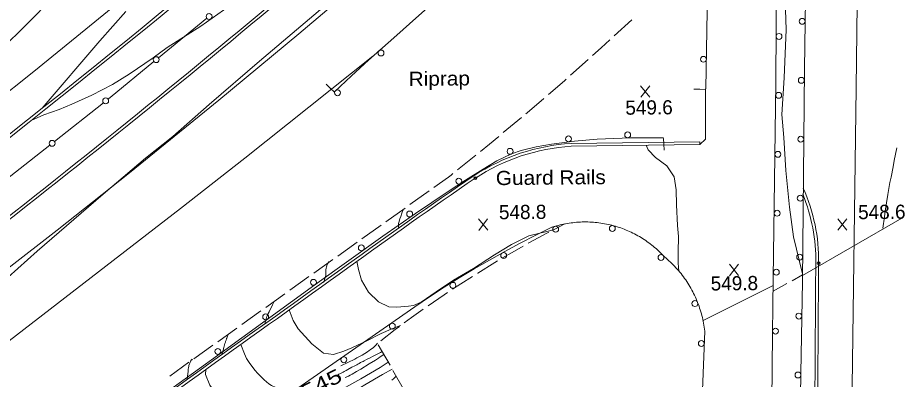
# Model space of a CAD drawing. Extents: x 2361284 to 2366480, y 6976556 to 6985346.
# Drawn here: x 2364184.5 to 2364482.3, y 6978961.5 to 6979084.2 of the extents above; entities that cross this region are included whole.
import ezdxf
from ezdxf.enums import TextEntityAlignment as Align

# ---------------------------------------------------------------- set-up
doc = ezdxf.new("R2010")
doc.units = 0
doc.header["$LTSCALE"] = 1.9
doc.header["$PDMODE"] = 32
doc.header["$PDSIZE"] = 0.95
for name, color, linetype, lineweight in [('12', 7, 'Continuous', 13), ('13', 7, 'Continuous', 13), ('14', 7, 'Continuous', 13), ('17', 7, 'Continuous', 13), ('24', 7, 'Continuous', 13), ('3', 7, 'Continuous', 13), ('5', 7, 'Continuous', 13), ('8', 7, 'Continuous', 13)]:
    doc.layers.add(name, color=color, linetype=linetype, lineweight=lineweight)

msp = doc.modelspace()

# ---------------------------------------------------------------- linework, layer by layer
at = {"layer": '12'}
for p, q in [((2364398.74, 6979057.25), (2364395.623, 6979061.101)), ((2364395.66, 6979057.221), (2364398.703, 6979061.13)), ((2364343.816, 6979012.086), (2364340.699, 6979015.937)), ((2364340.736, 6979012.057), (2364343.779, 6979015.966)), ((2364465.542, 6979012.113), (2364462.425, 6979015.964)), ((2364462.462, 6979012.084), (2364465.505, 6979015.993)), ((2364428.837, 6978996.693), (2364425.72, 6979000.544)), ((2364425.757, 6978996.664), (2364428.8, 6979000.573))]:
    msp.add_line(p, q, dxfattribs=at)
for points in [[(2364390.836, 6979256.813), (2364388.279, 6979254.359), (2364381.782, 6979248.668), (2364361.222, 6979231.731), (2364346.825, 6979220.903), (2364336.657, 6979213.196), (2364322.68, 6979202.352), (2364301.098, 6979184.517), (2364286.575, 6979173.257), (2364271.051, 6979161.92), (2364257.258, 6979150.698), (2364242.084, 6979137.233), (2364226.838, 6979123.107), (2364209.815, 6979105.355), (2364202.006, 6979096.9), (2364190.718, 6979085.091), (2364175.717, 6979070.308)], [(2364308.039, 6978970.921), (2364307.455, 6978970.626), (2364306.288, 6978970.035), (2364304.707, 6978969.231), (2364303.918, 6978968.828), (2364302.734, 6978968.221), (2364301.947, 6978967.815), (2364301.553, 6978967.611), (2364300.963, 6978967.304), (2364300.715, 6978967.174), (2364300.221, 6978966.913), (2364299.727, 6978966.651), (2364299.398, 6978966.474), (2364298.742, 6978966.12), (2364297.76, 6978965.585), (2364296.45, 6978964.871), (2364295.795, 6978964.515), (2364295.139, 6978964.16), (2364294.811, 6978963.984), (2364294.317, 6978963.721), (2364293.916, 6978963.51), (2364293.38, 6978963.23), (2364293.113, 6978963.089)], [(2364241.905, 6978961.452), (2364242.176, 6978963.465), (2364242.242, 6978964.098), (2364242.317, 6978964.944), (2364242.368, 6978965.367), (2364242.395, 6978965.529), (2364242.482, 6978965.909), (2364242.559, 6978966.19), (2364242.75, 6978966.783), (2364242.913, 6978967.221), (2364243.085, 6978967.62), (2364243.171, 6978967.796), (2364243.296, 6978968.021), (2364243.402, 6978968.173), (2364243.453, 6978968.229), (2364243.523, 6978968.285), (2364243.588, 6978968.305), (2364243.617, 6978968.3), (2364243.669, 6978968.257), (2364243.692, 6978968.219), (2364243.722, 6978968.14)], [(2364280.776, 6978956.42), (2364279.96, 6978955.963), (2364273.921, 6978952.605), (2364268.887, 6978949.857), (2364263.911, 6978948.44), (2364259.677, 6978948.83), (2364256.337, 6978950.918), (2364253.354, 6978954.28), (2364249.664, 6978959.525), (2364248.21, 6978963.132), (2364248.313, 6978964.863)]]:
    msp.add_lwpolyline(points, dxfattribs=at)
at = {"layer": '13'}
for points in [[(2364189.118, 6979049.315), (2364193.41, 6979051.236), (2364198.573, 6979053.035), (2364202.826, 6979054.845), (2364209.687, 6979057.9), (2364216.613, 6979061.546), (2364222.309, 6979065.07), (2364230.397, 6979070.598), (2364235.205, 6979074.095), (2364246.626, 6979081.363), (2364254.275, 6979086.755), (2364264.493, 6979094.404), (2364273.377, 6979101.289), (2364290.551, 6979115.803), (2364301.095, 6979123.833), (2364309.142, 6979129.48), (2364318.822, 6979136.882), (2364328.426, 6979143.884), (2364338.213, 6979151.557), (2364351.171, 6979162.372), (2364361.579, 6979171.05), (2364369.221, 6979177.283), (2364383.332, 6979186.649)], [(2364374.42, 6979177.413), (2364371.437, 6979173.564), (2364366.886, 6979168.361), (2364360.579, 6979161.601), (2364353.982, 6979154.957), (2364341.554, 6979140.949), (2364332.732, 6979131.734), (2364325.931, 6979124.399), (2364320.317, 6979118.526), (2364312.96, 6979111.774), (2364304.036, 6979102.7), (2364292.967, 6979092.024), (2364266.46, 6979069.42), (2364249.398, 6979054.798), (2364237.122, 6979043.94), (2364227.83, 6979036.592), (2364213.456, 6979024.384), (2364191.149, 6979005.012), (2364177.88, 6978993.245), (2364169.265, 6978985.383), (2364155.723, 6978972.782), (2364142.669, 6978960.479)], [(2364442.728, 6979133.74), (2364443.308, 6979130.686), (2364443.732, 6979123.889), (2364443.697, 6979117.019), (2364444.166, 6979105.623), (2364444.439, 6979093.695), (2364444.978, 6979080.169), (2364444.254, 6979063.751), (2364443.482, 6979051.334), (2364444.106, 6979043.508), (2364444.802, 6979032.394), (2364446.061, 6979019.866), (2364447.477, 6979009.849), (2364450.466, 6978997.307)], [(2364221.198, 6979086.261), (2364212.312, 6979076.337), (2364192.788, 6979053.48)], [(2364408.615, 6978998.209), (2364408.349, 6979000.865), (2364408.353, 6979004.627), (2364408.502, 6979010.018), (2364408.147, 6979013.675), (2364407.8, 6979020.732), (2364407.682, 6979025.801), (2364407.03, 6979030.185), (2364404.545, 6979033.992), (2364400.658, 6979036.815), (2364398.164, 6979039.351), (2364397.479, 6979040.915)], [(2364482.488, 6979040.007), (2364481.594, 6979035.738), (2364481.163, 6979033.6), (2364480.466, 6979030.051), (2364480.126, 6979028.274), (2364479.639, 6979025.605), (2364479.396, 6979024.19), (2364478.936, 6979021.355), (2364478.507, 6979018.516), (2364478.236, 6979016.621), (2364477.721, 6979012.827)], [(2364313.681, 6979012.887), (2364313.581, 6979013.253), (2364313.546, 6979013.439), (2364313.518, 6979013.716), (2364313.527, 6979013.991), (2364313.549, 6979014.126), (2364313.614, 6979014.425), (2364313.762, 6979015.02), (2364313.931, 6979015.614), (2364314.055, 6979016.008), (2364314.324, 6979016.793), (2364314.745, 6979017.919), (2364314.966, 6979018.474), (2364315.32, 6979019.303)], [(2364366.339, 6979012.398), (2364364.283, 6979011.818), (2364357.738, 6979010.236), (2364351.826, 6979007.199), (2364346.12, 6979003.744), (2364339.033, 6978999.057), (2364332.25, 6978995.153), (2364327.818, 6978992.24), (2364321.241, 6978987.658), (2364318.611, 6978986.573), (2364316.983, 6978986.317), (2364312.967, 6978985.959), (2364310.245, 6978986.093), (2364306.838, 6978987.841), (2364303.348, 6978991.028), (2364301.028, 6978995.176), (2364299.984, 6978998.816), (2364299.497, 6979001.571)], [(2364288.094, 6978994.553), (2364288.109, 6978994.491), (2364288.12, 6978994.461), (2364288.147, 6978994.428), (2364288.161, 6978994.425), (2364288.194, 6978994.441), (2364288.23, 6978994.487), (2364288.31, 6978994.654), (2364288.376, 6978994.835), (2364288.516, 6978995.293), (2364288.655, 6978995.816), (2364288.883, 6978996.74), (2364288.938, 6978997.027), (2364288.959, 6978997.219), (2364288.974, 6978997.603), (2364288.968, 6978997.987), (2364288.961, 6978998.5), (2364288.968, 6978998.756), (2364289.009, 6978999.14), (2364289.048, 6978999.331), (2364289.114, 6978999.574), (2364289.318, 6979000.18), (2364289.505, 6979000.653), (2364289.696, 6979001.061), (2364289.786, 6979001.217), (2364289.893, 6979001.357), (2364289.939, 6979001.391), (2364289.979, 6979001.397), (2364289.996, 6979001.389), (2364290.025, 6979001.349), (2364290.037, 6979001.317), (2364290.05, 6979001.251)], [(2364268.317, 6978980.383), (2364268.53, 6978981.288), (2364268.648, 6978981.738), (2364268.846, 6978982.405), (2364268.999, 6978982.844), (2364269.082, 6978983.061), (2364269.218, 6978983.383), (2364269.427, 6978983.807), (2364269.725, 6978984.359), (2364269.866, 6978984.639), (2364270.912, 6978986.829), (2364271.415, 6978987.934)], [(2364314.236, 6978979.73), (2364311.027, 6978978.519), (2364307.701, 6978977.047), (2364302.834, 6978974.621), (2364297.696, 6978972.162), (2364295.057, 6978971.038), (2364291.539, 6978969.884), (2364288.094, 6978970.382), (2364284.224, 6978973.524), (2364279.565, 6978978.61), (2364277.828, 6978981.464), (2364276.512, 6978985.072)], [(2364253.646, 6978969.864), (2364253.803, 6978970.368), (2364253.907, 6978970.705), (2364254.112, 6978971.378), (2364254.209, 6978971.7), (2364254.272, 6978971.915), (2364254.397, 6978972.346), (2364254.765, 6978973.64), (2364254.89, 6978974.071), (2364254.954, 6978974.286), (2364254.984, 6978974.384), (2364255.046, 6978974.58), (2364255.111, 6978974.775), (2364255.156, 6978974.904), (2364255.249, 6978975.161), (2364255.321, 6978975.353), (2364255.371, 6978975.481), (2364255.472, 6978975.735), (2364255.523, 6978975.862), (2364255.628, 6978976.116), (2364255.734, 6978976.369), (2364255.95, 6978976.875)], [(2364278.147, 6978958.386), (2364277.559, 6978958.23), (2364276.379, 6978958.089), (2364274.434, 6978958.129), (2364273.46, 6978958.285), (2364272.003, 6978958.737), (2364270.55, 6978959.451), (2364269.674, 6978960.012), (2364268.048, 6978961.331), (2364265.915, 6978963.455), (2364264.928, 6978964.591), (2364262.947, 6978967.172), (2364262.1, 6978968.564), (2364261.335, 6978970.11), (2364260.095, 6978973.305)], [(2364306.422, 6978973.765), (2364305.972, 6978973.221), (2364305.738, 6978972.959), (2364305.371, 6978972.583), (2364304.977, 6978972.233), (2364304.768, 6978972.069), (2364304.013, 6978971.518), (2364303.632, 6978971.251), (2364303.056, 6978970.859), (2364302.182, 6978970.294), (2364301.295, 6978969.754), (2364300.846, 6978969.494), (2364299.938, 6978968.993), (2364299.478, 6978968.753), (2364298.782, 6978968.403), (2364294.065, 6978966.098)], [(2364308.599, 6978969.937), (2364307.39, 6978969.126), (2364306.78, 6978968.729), (2364305.734, 6978968.063), (2364303.629, 6978966.749), (2364300.773, 6978964.98), (2364299.334, 6978964.114), (2364297.879, 6978963.274), (2364297.144, 6978962.867), (2364296.599, 6978962.594), (2364295.859, 6978962.257), (2364295.492, 6978962.082)], [(2364310.094, 6978967.311), (2364307.361, 6978965.485), (2364300.827, 6978961.692), (2364294.749, 6978958.233), (2364283.845, 6978952.339), (2364276.756, 6978947.872), (2364270.744, 6978944.895), (2364264.9, 6978942.21), (2364257.222, 6978937.836), (2364250.828, 6978934.915), (2364243.071, 6978931.401), (2364238.186, 6978929.914), (2364233.872, 6978929.283), (2364230.815, 6978929.874), (2364226.961, 6978931.318), (2364223.077, 6978933.891), (2364219.899, 6978936.801), (2364218.379, 6978938.837), (2364217.621, 6978942.899)], [(2364311.416, 6978964.983), (2364308.154, 6978963.122), (2364302.186, 6978959.634), (2364294.819, 6978955.094), (2364287.877, 6978951.128), (2364281.245, 6978948.125), (2364274.609, 6978944.361), (2364268.898, 6978941.378), (2364257.114, 6978935.485), (2364248.364, 6978930.041), (2364237.737, 6978925.62), (2364232.314, 6978922.668), (2364226.59, 6978919.904), (2364223.296, 6978919.262), (2364220.193, 6978919.583), (2364217.032, 6978920.683), (2364213.178, 6978923.136), (2364209.185, 6978926.608), (2364206.942, 6978928.997), (2364206.122, 6978930.039), (2364204.857, 6978933.768)], [(2364312.789, 6978962.566), (2364312.144, 6978961.939), (2364311.814, 6978961.634), (2364311.31, 6978961.188)]]:
    msp.add_lwpolyline(points, dxfattribs=at)
at = {"layer": '14'}
for points in [[(2364471.751, 6979300.826), (2364470.266, 6979192.976), (2364468.687, 6979060.443), (2364467.19, 6978950.713), (2364465.398, 6978823.599), (2364465.014, 6978782.341), (2364464.713, 6978727.329), (2364464.476, 6978699.823), (2364463.104, 6978583.283), (2364461.505, 6978460.062), (2364461.304, 6978437.786), (2364461.091, 6978393.234)], [(2364420.159, 6979267.113), (2364400.723, 6979248.336), (2364390.885, 6979239.073), (2364367.462, 6979217.462), (2364355.655, 6979206.764), (2364337.799, 6979190.876), (2364315.598, 6979171.486), (2364300.731, 6979158.638), (2364270.855, 6979133.106), (2364244.209, 6979110.62), (2364230.829, 6979099.447), (2364210.669, 6979082.791), (2364189.937, 6979065.945), (2364176.031, 6979054.822), (2364148.013, 6979032.833), (2364126.906, 6979016.585), (2364112.779, 6979005.83), (2364084.388, 6978984.496), (2364056.021, 6978963.478), (2364041.79, 6978953.033), (2364020.372, 6978937.464), (2363990.222, 6978915.934), (2363975.045, 6978905.311), (2363972.005, 6978903.232)], [(2363951.494, 6978832.723), (2363965.118, 6978841.916), (2363992.242, 6978860.482), (2364021.619, 6978880.939), (2364036.247, 6978891.253), (2364058.115, 6978906.831), (2364078.805, 6978921.811), (2364092.528, 6978931.892), (2364119.847, 6978952.23), (2364146.002, 6978972.008), (2364163.349, 6978985.309), (2364197.851, 6979012.166), (2364222.356, 6979031.614), (2364234.536, 6979041.425), (2364252.715, 6979056.252), (2364279.783, 6979078.749), (2364309.686, 6979104.155), (2364329.473, 6979121.256), (2364342.603, 6979132.728), (2364368.725, 6979155.838), (2364391.388, 6979176.238), (2364402.645, 6979186.517), (2364419.438, 6979202.042)]]:
    msp.add_lwpolyline(points, dxfattribs=at)
at = {"layer": '17'}
for points in [[(2364417.758, 6979060.079), (2364418.136, 6979086.513), (2364418.465, 6979112.948), (2364419.076, 6979168.637), (2364419.686, 6979224.326), (2364420.178, 6979269.333), (2364420.68, 6979314.33)], [(2364444.353, 6979307.846), (2364443.795, 6979259.247), (2364443.147, 6979210.649), (2364442.492, 6979174.41), (2364441.856, 6979138.163), (2364441.648, 6979100.168), (2364441.439, 6979062.174), (2364441.005, 6979028.918), (2364440.571, 6978995.663), (2364440.44, 6978986.341), (2364440.319, 6978977.008), (2364439.788, 6978919.211), (2364439.328, 6978861.403), (2364438.813, 6978806.165), (2364438.298, 6978750.917), (2364438.11, 6978727.544), (2364437.983, 6978704.162), (2364438.297, 6978676.313), (2364438.802, 6978648.466), (2364438.849, 6978604.574), (2364438.917, 6978560.692), (2364439.979, 6978526.851), (2364441.96, 6978493.038)], [(2364446.359, 6978672.98), (2364446.68, 6978699.164), (2364446.981, 6978725.358), (2364447.359, 6978766.605), (2364447.757, 6978807.84), (2364448.554, 6978870.221), (2364449.441, 6978932.593), (2364449.946, 6978963.65), (2364450.441, 6978994.716), (2364450.787, 6979030.811), (2364451.104, 6979066.906), (2364451.74, 6979106.275), (2364452.316, 6979145.642), (2364452.656, 6979190.848), (2364452.936, 6979236.063), (2364453.125, 6979270.877), (2364453.304, 6979305.691)], [(2364419.118, 6979172.568), (2364406.627, 6979160.979), (2364393.976, 6979149.567), (2364371.442, 6979129.902), (2364348.918, 6979110.207), (2364334.677, 6979097.561), (2364320.436, 6979084.904), (2364311.928, 6979077.354), (2364303.419, 6979069.802), (2364297.588, 6979064.496), (2364291.84, 6979059.101)], [(2364179.059, 6978918.752), (2364186.392, 6978923.582), (2364193.707, 6978928.451), (2364205.98, 6978936.638), (2364218.11, 6978945.034), (2364235.166, 6978957.307), (2364252.188, 6978969.62), (2364268.715, 6978981.587), (2364285.243, 6978993.556), (2364296.754, 6979001.844), (2364308.287, 6979010.105), (2364319.305, 6979017.751), (2364330.424, 6979025.247), (2364336.288, 6979029.073), (2364342.223, 6979032.809), (2364346.917, 6979035.584), (2364351.864, 6979037.981), (2364355.173, 6979039.173), (2364360.241, 6979040.441), (2364365.403, 6979041.31), (2364373.154, 6979042.354), (2364380.937, 6979043.038), (2364392.134, 6979043.484), (2364403.335, 6979043.431)], [(2364372.038, 6979014.582), (2364371.409, 6979014.496), (2364370.78, 6979014.39), (2364370.161, 6979014.284), (2364369.532, 6979014.158), (2364368.913, 6979014.022), (2364368.305, 6979013.876), (2364367.686, 6979013.73), (2364367.078, 6979013.565), (2364366.469, 6979013.389), (2364365.86, 6979013.203), (2364365.521, 6979013.09), (2364360.136, 6979010.458), (2364354.842, 6979007.728), (2364349.599, 6979004.898), (2364344.347, 6979001.987), (2364339.184, 6978998.979), (2364334.103, 6978995.89), (2364329.023, 6978992.722), (2364324.024, 6978989.444), (2364319.126, 6978986.097)], [(2364417.349, 6978977.9), (2364417.273, 6978978.559), (2364417.176, 6978979.218), (2364417.07, 6978979.877), (2364416.954, 6978980.536), (2364416.828, 6978981.195), (2364416.691, 6978981.844), (2364416.545, 6978982.494), (2364416.379, 6978983.142), (2364416.213, 6978983.78), (2364416.027, 6978984.429), (2364415.831, 6978985.067), (2364415.625, 6978985.695), (2364415.409, 6978986.333), (2364415.183, 6978986.951), (2364414.947, 6978987.579), (2364414.701, 6978988.196), (2364414.435, 6978988.814), (2364414.169, 6978989.421), (2364413.884, 6978990.029), (2364413.588, 6978990.626), (2364413.292, 6978991.223), (2364412.977, 6978991.81), (2364412.651, 6978992.387), (2364412.326, 6978992.964), (2364411.98, 6978993.541), (2364411.625, 6978994.107), (2364411.259, 6978994.664), (2364410.894, 6978995.22), (2364410.509, 6978995.767), (2364410.113, 6978996.303), (2364409.718, 6978996.839), (2364409.313, 6978997.365), (2364408.888, 6978997.881), (2364408.463, 6978998.387), (2364408.028, 6978998.893), (2364407.573, 6978999.389), (2364407.119, 6978999.875), (2364406.664, 6979000.359), (2364406.191, 6979000.825), (2364405.706, 6979001.29), (2364405.222, 6979001.746), (2364404.727, 6979002.191), (2364404.223, 6979002.636), (2364403.709, 6979003.061), (2364403.558, 6979003.19), (2364403.123, 6979003.656), (2364402.679, 6979004.112), (2364402.235, 6979004.548), (2364401.781, 6979004.994), (2364401.317, 6979005.43), (2364400.843, 6979005.845), (2364400.369, 6979006.261), (2364399.875, 6979006.666), (2364399.381, 6979007.061), (2364398.877, 6979007.457), (2364398.374, 6979007.832), (2364397.87, 6979008.207), (2364397.346, 6979008.572), (2364396.823, 6979008.917), (2364396.29, 6979009.262), (2364395.747, 6979009.597), (2364395.204, 6979009.922), (2364394.661, 6979010.237), (2364394.098, 6979010.541), (2364393.545, 6979010.846), (2364392.972, 6979011.131), (2364392.409, 6979011.405), (2364391.827, 6979011.67), (2364391.254, 6979011.924), (2364390.672, 6979012.169), (2364390.08, 6979012.413), (2364389.487, 6979012.638), (2364388.895, 6979012.852), (2364388.293, 6979013.056), (2364387.691, 6979013.251), (2364387.079, 6979013.435), (2364386.477, 6979013.609), (2364385.866, 6979013.773), (2364385.244, 6979013.917), (2364384.633, 6979014.062), (2364384.011, 6979014.196), (2364383.38, 6979014.31), (2364382.759, 6979014.424), (2364382.138, 6979014.518), (2364381.507, 6979014.602), (2364380.877, 6979014.686), (2364380.246, 6979014.74), (2364379.615, 6979014.804), (2364378.985, 6979014.838), (2364378.356, 6979014.872), (2364377.725, 6979014.896), (2364377.085, 6979014.9), (2364376.455, 6979014.904), (2364375.825, 6979014.888), (2364375.186, 6979014.862), (2364374.556, 6979014.836), (2364373.926, 6979014.79), (2364373.297, 6979014.724), (2364372.667, 6979014.658), (2364372.038, 6979014.582)], [(2364319.126, 6978986.097), (2364293.911, 6978968.587), (2364268.695, 6978951.075), (2364223.262, 6978919.672), (2364177.879, 6978888.188), (2364129.919, 6978854.212), (2364082.122, 6978819.995), (2364034.524, 6978785.94), (2363986.965, 6978751.846), (2363968.451, 6978738.519), (2363950.251, 6978724.765), (2363950.112, 6978724.654), (2363949.973, 6978724.533)], [(2364421.077, 6978403.814), (2364418.826, 6978449.135), (2364416.795, 6978494.459), (2364414.788, 6978545.683), (2364413.361, 6978596.922), (2364413.088, 6978633.012), (2364413.335, 6978669.105), (2364413.585, 6978689.099), (2364413.835, 6978709.092), (2364414.558, 6978774.993), (2364415.271, 6978840.903), (2364415.811, 6978889.38), (2364416.37, 6978937.859), (2364416.569, 6978957.882), (2364417.349, 6978977.9)]]:
    msp.add_lwpolyline(points, dxfattribs=at)
for centre in [(2364450.365, 6979082.968), (2364442.525, 6979077.858), (2364307.638, 6979072.21), (2364416.9, 6979070.092), (2364450.07, 6979062.962), (2364292.903, 6979058.728), (2364442.383, 6979057.851), (2364371.18, 6979043.094), (2364391.218, 6979044.453), (2364449.897, 6979042.963), (2364351.373, 6979038.855), (2364442.125, 6979037.852), (2364333.985, 6979028.763), (2364449.715, 6979022.965), (2364317.349, 6979017.611), (2364441.864, 6979017.853), (2364366.818, 6979012.447), (2364386.033, 6979012.69), (2364300.975, 6979006.101), (2364349.188, 6979003.527), (2364402.51, 6979002.849), (2364449.521, 6979002.965), (2364441.6, 6978997.855), (2364284.735, 6978994.422), (2364332.006, 6978993.399), (2364414.015, 6978987.207), (2364449.253, 6978982.973), (2364268.534, 6978982.691), (2364311.484, 6978979.57), (2364441.33, 6978977.857), (2364416.182, 6978973.667), (2364252.335, 6978970.961), (2364295.058, 6978968.159), (2364448.933, 6978962.976)]:
    msp.add_circle(centre, 1, dxfattribs=at)
at = {"layer": '24'}
for p, q in [((2364392.584, 6979083.511), (2364386.704, 6979078.095)), ((2364377.831, 6979070.019), (2364371.892, 6979064.663)), ((2364355.227, 6979050.305), (2364349.066, 6979045.205)), ((2364339.787, 6979037.596), (2364333.575, 6979032.557)), ((2364323.912, 6979025.445), (2364317.406, 6979020.793)), ((2364315.777, 6979019.627), (2364309.271, 6979014.975)), ((2364307.642, 6979013.809), (2364301.136, 6979009.157)), ((2364369.891, 6979014.231), (2364366.339, 6979012.398)), ((2364299.506, 6979007.992), (2364292.991, 6979003.339)), ((2364291.362, 6979002.173), (2364284.845, 6978997.532)), ((2364283.216, 6978996.366), (2364276.709, 6978991.714)), ((2364450.46, 6978996.917), (2364446.968, 6978994.973)), ((2364445.217, 6978993.997), (2364440.512, 6978991.382)), ((2364275.08, 6978990.559), (2364268.574, 6978985.907)), ((2364266.945, 6978984.741), (2364260.44, 6978980.088)), ((2364258.811, 6978978.923), (2364252.304, 6978974.271)), ((2364250.675, 6978973.105), (2364244.169, 6978968.454)), ((2364306.727, 6978973.228), (2364310.684, 6978966.276)), ((2364242.54, 6978967.288), (2364236.035, 6978962.636)), ((2364311.67, 6978964.536), (2364315.627, 6978957.582))]:
    msp.add_line(p, q, dxfattribs=at)
for points in [[(2364385.237, 6979076.741), (2364382.263, 6979074.003), (2364379.318, 6979071.355)], [(2364370.405, 6979063.318), (2364369.82, 6979062.793), (2364364.353, 6979058.091)], [(2364362.836, 6979056.786), (2364357.162, 6979051.913), (2364356.765, 6979051.579)], [(2364347.528, 6979043.93), (2364344.363, 6979041.31), (2364341.335, 6979038.861)], [(2364332.016, 6979031.302), (2364331.361, 6979030.766), (2364330.468, 6979030.127), (2364325.541, 6979026.61)], [(2364364.556, 6979011.481), (2364363.86, 6979011.124), (2364357.92, 6979007.887), (2364357.522, 6979007.663)], [(2364355.782, 6979006.677), (2364352.052, 6979004.551), (2364348.85, 6979002.68)], [(2364347.12, 6979001.673), (2364346.175, 6979001.124), (2364340.397, 6978997.58), (2364340.288, 6978997.509)], [(2364338.598, 6978996.433), (2364334.712, 6978993.946), (2364331.879, 6978992.099)], [(2364330.209, 6978991.003), (2364329.027, 6978990.232), (2364323.602, 6978986.5)], [(2364321.974, 6978985.334), (2364317.96, 6978982.466), (2364315.497, 6978980.642)], [(2364313.889, 6978979.456), (2364312.488, 6978978.423), (2364307.524, 6978974.606)]]:
    msp.add_lwpolyline(points, dxfattribs=at)
at = {"layer": '3'}
for p, q in [((2364415.718, 6979041.148), (2364415.708, 6979042.108)), ((2364339.059, 6979030.556), (2364339.076, 6979030.567)), ((2364295.848, 6979000.121), (2364295.846, 6979000.12)), ((2364296.407, 6978999.341), (2364296.408, 6978999.342)), ((2364454.982, 6979000.954), (2364454.982, 6979000.962))]:
    msp.add_line(p, q, dxfattribs=at)
for points in [[(2364304.877, 6979071.097), (2364261.483, 6979036.532), (2364239.634, 6979019.443), (2364142.344, 6978944.234), (2364072.224, 6978890.134), (2364061.065, 6978881.712), (2364053.55, 6978876.2), (2364038.361, 6978865.392), (2364030.698, 6978860.082), (2364015.262, 6978849.617), (2363999.713, 6978839.314), (2363968.446, 6978818.974), (2363952.175, 6978808.479)], [(2364415.718, 6979041.148), (2364417.651, 6979042.947), (2364417.648, 6979060.077)], [(2364372.049, 6979041.552), (2364372.102, 6979041.554), (2364415.708, 6979042.108)], [(2364372.11, 6979040.594), (2364372.111, 6979040.594), (2364415.718, 6979041.148)]]:
    msp.add_lwpolyline(points, dxfattribs=at)
for centre, radius, start, end in [((2361757.968, 6982101.757), 3923.052, 307.14611, 311.3083), ((2361757.968, 6982101.757), 3924.012, 307.14611, 311.3083), ((2361158.91, 6982851.448), 4860.97, 307.20262, 309.88554), ((2361158.91, 6982851.448), 4861.93, 307.20262, 309.88554), ((2364376.381, 6978973.568), 68.122, 93.6454, 123.20363), ((2364376.381, 6978973.568), 67.162, 93.6454, 123.20363), ((2365502.997, 6977332.122), 2058.987, 124.42288, 125.89376), ((2365502.997, 6977332.122), 2058.027, 124.42288, 125.89376), ((2364395.141, 6979001.766), 60.807, 359.22947, 23.90902), ((2364395.141, 6979001.766), 59.847, 359.22946, 22.12311), ((2324890.554, 7033921.505), 67595.381, 305.55919, 305.65889), ((2324890.554, 7033921.505), 67596.342, 305.55919, 305.65889), ((2344543.782, 6979107.331), 19911.484, 358.87892, 359.6939), ((2344543.782, 6979107.331), 19912.444, 358.87892, 359.6939)]:
    msp.add_arc(centre, radius, start, end, dxfattribs=at)
for p in [(2364339.602, 6979029.764), (2364455.942, 6979000.949)]:
    msp.add_point(p, dxfattribs=at)
at = {"layer": '5'}
for p, q in [((2364232.277, 6979070.636), (2364248.61, 6979084.011)), ((2364197.005, 6979042.249), (2364213.541, 6979055.367))]:
    msp.add_line(p, q, dxfattribs=at)
for points in [[(2364215.1, 6979056.602), (2364215.814, 6979057.168), (2364230.689, 6979069.34)], [(2364291.85, 6979058.912), (2364290.43, 6979060.306), (2364289.002, 6979061.706)], [(2364417.648, 6979059.878), (2364415.658, 6979059.922), (2364413.659, 6979059.967)], [(2364179.595, 6979028.503), (2364183.783, 6979031.753), (2364195.397, 6979040.974)], [(2364403.335, 6979043.232), (2364403.478, 6979041.247), (2364403.621, 6979039.252)]]:
    msp.add_lwpolyline(points, dxfattribs=at)
for centre in [(2364249.373, 6979084.633), (2364231.45, 6979069.965), (2364214.313, 6979055.978), (2364196.172, 6979041.58)]:
    msp.add_circle(centre, 1, dxfattribs=at)
at = {"layer": '8'}
for p, q in [((2364484.149, 6979016.218), (2364450.462, 6978996.717)), ((2364440.544, 6978993.292), (2364416.775, 6978981.485))]:
    msp.add_line(p, q, dxfattribs=at)

# ---------------------------------------------------------------- texts
at = {"layer": '12'}
for s, p in [('549.6', (2364390.46, 6979051.28)), ('548.8', (2364347.625, 6979015.81)), ('548.6', (2364469.351, 6979015.837)), ('549.8', (2364419.378, 6978991.641))]:
    msp.add_text(s, height=4.799, rotation=0.545, dxfattribs=at).set_placement(p)
at = {"layer": '12', "width": 1.35}
msp.add_text(' 545 ', height=4.799, rotation=26.398, dxfattribs=at).set_placement((2364288.494, 6978957.865), align=Align.CENTER)
at = {"layer": '17', "width": 1.1}
msp.add_text('Guard Rails', height=4.799, rotation=0.545, dxfattribs=at).set_placement((2364346.555, 6979027.391))
at = {"layer": '24', "width": 1.1}
msp.add_text('Riprap', height=4.799, rotation=0.545, dxfattribs=at).set_placement((2364317.013, 6979061.041))

doc.saveas('drawing.dxf')
